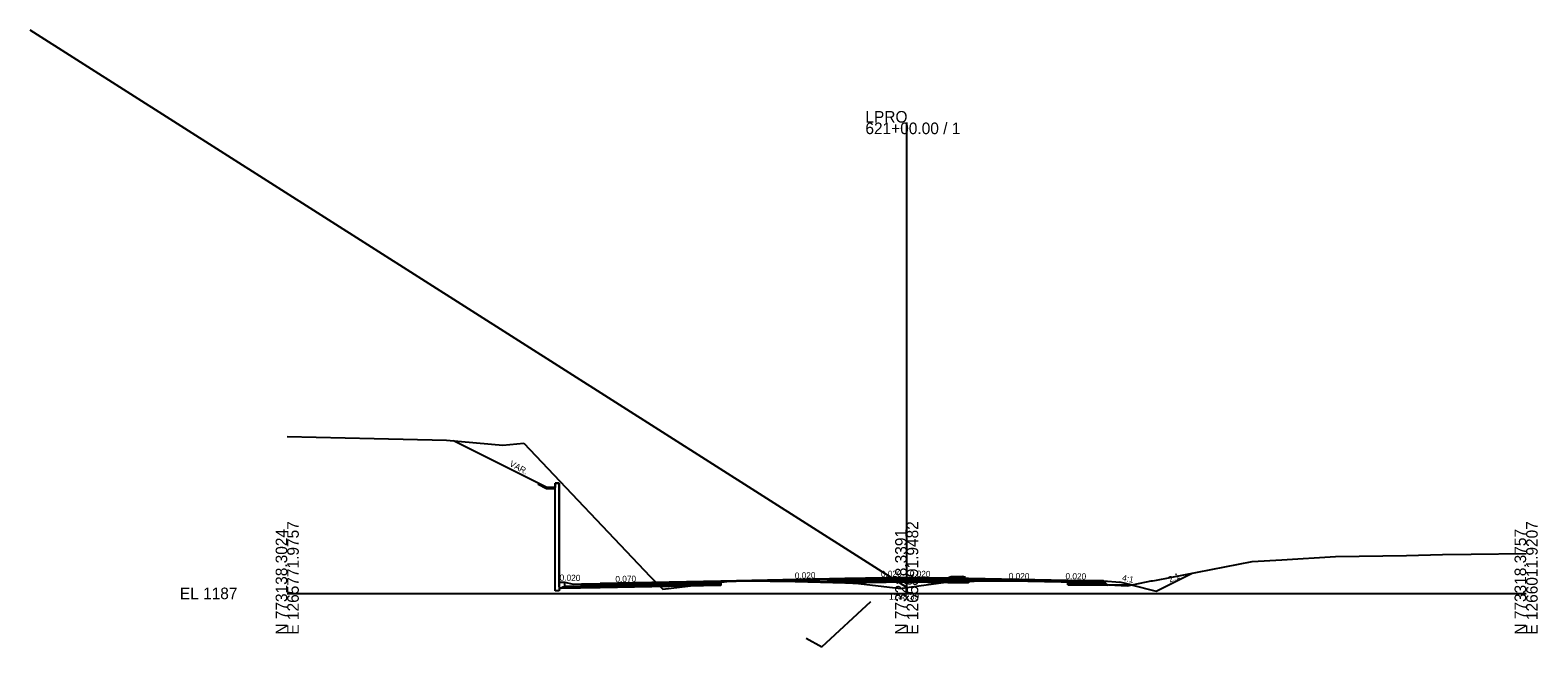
# Model space of a CAD drawing. Extents: x -3833 to 1267678, y -522 to 773248.
# Drawn here: x 2937.8 to 3302.8, y 1987 to 2136.5 of the extents above; entities that cross this region are included whole.
import ezdxf

# ---------------------------------------------------------------- set-up
doc = ezdxf.new("R2010")
doc.units = 0
for name, color, linetype in [('Exist Cross Section Cell', 7, 'Continuous'), ('Exist XS Center Line Elevation Label', 7, 'Continuous'), ('Exist XS Ground Line', 7, 'Continuous'), ('Prop CMT DNC', 7, 'Continuous'), ('Prop CMT Pvmt Course 1', 7, 'Continuous'), ('Prop CMT Pvmt Course 2', 7, 'Continuous'), ('Prop CMT Pvmt Course 3', 7, 'Continuous'), ('Prop CMT Pvmt Course 4', 7, 'Continuous'), ('Prop CMT Shld Paved Course 1', 7, 'Continuous'), ('Prop CMT Shld Paved Course 2', 7, 'Continuous'), ('Prop CMT Shld Paved Course 4', 7, 'Continuous'), ('Prop CMT Slope Grass', 7, 'Continuous'), ('Prop CMT Subgrade Earthwork', 7, 'Continuous'), ('Prop Conc Curb and Gutter', 7, 'Continuous'), ('Prop Corridor Mesh Bottom', 7, 'Continuous'), ('Prop XS Ditch Slope Text', 7, 'Continuous'), ('Prop XS Finish Grade', 7, 'Continuous'), ('Prop XS SE Text', 7, 'Continuous'), ('Scratch_Level_1', 7, 'Continuous'), ('Scratch_Level_5', 7, 'Continuous')]:
    doc.layers.add(name, color=color, linetype=linetype)

msp = doc.modelspace()

# ---------------------------------------------------------------- linework, layer by layer
at = {"layer": 'Exist Cross Section Cell'}
for p, q in [((3150, 2000), (3150, 2114.06)), ((3000, 2000), (3150, 2000)), ((3150, 2000), (3300, 2000))]:
    msp.add_line(p, q, dxfattribs=at)
at = {"layer": 'Exist XS Ground Line'}
for p, q in [((3000, 2038.02), (3021.03, 2037.5)), ((3021.03, 2037.5), (3038.61, 2037.13)), ((3038.61, 2037.13), (3052.2, 2035.94)), ((3052.2, 2035.94), (3057.28, 2036.42)), ((3057.28, 2036.42), (3087.88, 2004.09)), ((3233.63, 2007.72), (3240.83, 2008.12)), ((3240.83, 2008.12), (3253.88, 2008.93)), ((3253.88, 2008.93), (3271.06, 2009.2)), ((3271.06, 2009.2), (3279.79, 2009.39)), ((3279.79, 2009.39), (3286.72, 2009.51)), ((3286.72, 2009.51), (3300, 2009.69)), ((3210.49, 2003.24), (3233.63, 2007.72)), ((3087.88, 2004.09), (3090.95, 2001.04)), ((3090.95, 2001.04), (3106.44, 2002.87)), ((3106.44, 2002.87), (3111.02, 2003.02)), ((3111.02, 2003.02), (3122.99, 2002.92)), ((3122.99, 2002.92), (3135.22, 2002.58)), ((3135.22, 2002.58), (3135.62, 2002.57)), ((3135.62, 2002.57), (3138.31, 2002.42)), ((3138.31, 2002.42), (3148.58, 2001.2)), ((3148.58, 2001.2), (3149.02, 2001.26)), ((3149.02, 2001.26), (3150, 2001.39)), ((3150, 2001.39), (3152.94, 2001.8)), ((3152.94, 2001.8), (3159.49, 2002.7)), ((3159.49, 2002.7), (3160.28, 2002.81)), ((3160.28, 2002.81), (3163.99, 2002.94)), ((3163.99, 2002.94), (3175, 2003.06)), ((3175, 2003.06), (3175.33, 2003.07)), ((3175.33, 2003.07), (3187.65, 2002.83)), ((3187.65, 2002.83), (3188.99, 2002.76)), ((3188.99, 2002.76), (3197.35, 2002.15)), ((3197.35, 2002.15), (3203.47, 2001.86)), ((3203.47, 2001.86), (3209.19, 2003.04)), ((3209.19, 2003.04), (3209.56, 2003.08)), ((3209.56, 2003.08), (3210.49, 2003.24))]:
    msp.add_line(p, q, dxfattribs=at)
at = {"layer": 'Prop CMT Pvmt Course 1'}
for p, q in [((3135, 2003.58), (3105, 2002.98)), ((3105, 2002.98), (3105, 2002.98)), ((3105, 2002.98), (3105, 2002.73)), ((3105, 2002.73), (3106.42, 2002.88)), ((3105, 2002.73), (3105, 2002.73)), ((3105, 2002.73), (3105, 2002.73)), ((3106.42, 2002.88), (3110.92, 2003.04)), ((3110.92, 2003.04), (3135, 2003.33)), ((3135, 2003.33), (3135, 2003.58)), ((3135, 2003.33), (3135, 2003.33)), ((3159.5, 2003.69), (3159.5, 2003.69)), ((3159.5, 2003.69), (3159.5, 2003.44)), ((3159.5, 2003.44), (3159.5, 2003.44)), ((3159.5, 2003.44), (3159.5, 2003.44)), ((3160.25, 2003.42), (3160.25, 2003.7)), ((3160.25, 2003.45), (3160.25, 2003.45)), ((3165, 2003.58), (3164.25, 2003.59)), ((3164.25, 2003.59), (3164.25, 2003.34)), ((3164.25, 2003.34), (3164.25, 2003.34)), ((3164.25, 2003.34), (3165, 2003.33)), ((3189, 2003.1), (3165, 2003.58)), ((3165, 2003.58), (3165, 2003.33)), ((3165, 2003.33), (3165, 2003.58)), ((3165, 2003.58), (3165, 2003.58)), ((3165, 2003.33), (3165, 2003.33)), ((3165, 2003.33), (3189, 2002.85)), ((3165, 2003.33), (3165, 2003.33)), ((3165, 2003.33), (3165, 2003.33)), ((3189, 2002.85), (3189, 2003.1)), ((3189, 2003.1), (3189, 2003.1)), ((3189, 2002.85), (3189, 2002.85)), ((3189, 2002.85), (3189, 2002.85))]:
    msp.add_line(p, q, dxfattribs=at)
at = {"layer": 'Prop CMT Pvmt Course 2'}
for p, q in [((3150, 2003.63), (3135, 2003.33)), ((3135, 2003.33), (3135, 2003.33)), ((3135, 2003.33), (3135, 2003)), ((3135, 2002.99), (3150, 2003.3)), ((3135, 2003), (3135, 2003)), ((3135, 2003), (3135, 2002.99)), ((3135, 2002.99), (3135, 2002.99)), ((3135, 2002.99), (3135, 2002.99)), ((3165, 2003.33), (3150, 2003.63)), ((3150, 2003.3), (3165, 2002.99)), ((3159.5, 2003.44), (3159.5, 2003.44)), ((3159.5, 2003.44), (3159.5, 2003.19)), ((3159.5, 2003.19), (3159.5, 2003.19)), ((3159.5, 2003.19), (3159.5, 2003.19)), ((3160.25, 2003.09), (3160.25, 2003.42)), ((3160.25, 2003.2), (3160.25, 2003.2)), ((3165, 2003.33), (3164.25, 2003.34)), ((3164.25, 2003.34), (3164.25, 2003.09)), ((3164.25, 2003.09), (3164.25, 2003.09)), ((3165, 2002.99), (3165, 2003.33)), ((3165, 2003.33), (3165, 2003.33)), ((3165, 2003.08), (3165, 2003.33)), ((3165, 2003.33), (3165, 2003.33)), ((3165, 2003.08), (3165, 2003.08)), ((3165, 2003.08), (3165, 2003.08)), ((3165, 2002.99), (3165, 2002.99)), ((3165, 2002.99), (3165, 2002.99)), ((3165, 2002.99), (3165, 2002.99))]:
    msp.add_line(p, q, dxfattribs=at)
at = {"layer": 'Prop CMT Pvmt Course 3'}
for p, q in [((3159.5, 2003.19), (3159.5, 2003.19)), ((3159.5, 2003.19), (3159.5, 2002.65)), ((3159.5, 2002.81), (3159.5, 2002.81)), ((3159.5, 2002.81), (3159.5, 2002.81)), ((3160.25, 2002.83), (3160.25, 2003.2)), ((3160.25, 2002.83), (3160.25, 2002.83)), ((3164.25, 2003.09), (3164.25, 2002.72)), ((3164.25, 2002.72), (3164.25, 2002.72)), ((3165, 2002.7), (3165, 2003.08)), ((3165, 2003.08), (3165, 2003.08)), ((3165, 2002.7), (3165, 2002.7)), ((3165, 2002.7), (3165, 2002.7))]:
    msp.add_line(p, q, dxfattribs=at)
at = {"layer": 'Prop CMT Pvmt Course 4'}
for p, q in [((3150, 2003.3), (3135, 2002.99)), ((3135, 2002.99), (3135, 2003)), ((3135, 2003), (3135, 2002.53)), ((3135, 2002.99), (3135, 2002.99)), ((3135, 2002.99), (3135, 2002.99)), ((3135, 2002.53), (3150.01, 2002.84)), ((3165, 2002.99), (3150, 2003.3)), ((3150, 2002.84), (3165, 2002.53)), ((3159.5, 2002.81), (3159.5, 2002.81)), ((3159.5, 2002.81), (3159.5, 2002.65)), ((3160.25, 2002.63), (3160.25, 2002.83)), ((3164.25, 2002.72), (3164.25, 2002.55)), ((3165, 2002.53), (3165, 2002.99)), ((3165, 2002.99), (3165, 2002.99)), ((3165, 2002.99), (3165, 2002.99)), ((3165, 2002.53), (3165, 2002.7)), ((3165, 2002.7), (3165, 2002.7))]:
    msp.add_line(p, q, dxfattribs=at)
at = {"layer": 'Prop CMT Shld Paved Course 1'}
for p, q in [((3071.24, 2002.3), (3075.79, 2002.39)), ((3071.24, 2002.05), (3071.24, 2002.3)), ((3075.79, 2002.14), (3071.24, 2002.05)), ((3071.24, 2002.05), (3071.24, 2002.05)), ((3105, 2002.98), (3075.79, 2002.39)), ((3075.79, 2002.14), (3105, 2002.73)), ((3075.79, 2002.39), (3075.79, 2002.39)), ((3075.79, 2002.39), (3075.79, 2002.14)), ((3075.79, 2002.39), (3075.79, 2002.14)), ((3075.79, 2002.14), (3075.79, 2002.14)), ((3075.79, 2002.14), (3075.79, 2002.14)), ((3105, 2002.73), (3105, 2002.98)), ((3150, 2003.88), (3135, 2003.58)), ((3135, 2003.33), (3150, 2003.63)), ((3135, 2003.58), (3135, 2003.58)), ((3135, 2003.58), (3135, 2003.33)), ((3135, 2003.33), (3135, 2003.33)), ((3135, 2003.33), (3135, 2003.33)), ((3160.25, 2003.67), (3150, 2003.88)), ((3150, 2003.63), (3165, 2003.33)), ((3165, 2003.58), (3164.25, 2003.59)), ((3165, 2003.33), (3165, 2003.58)), ((3165, 2003.58), (3165, 2003.58)), ((3165, 2003.33), (3165, 2003.33)), ((3165, 2003.33), (3165, 2003.33)), ((3189, 2003.1), (3189, 2002.85)), ((3197.65, 2003.02), (3189, 2003.1)), ((3189, 2002.85), (3197.9, 2002.77)), ((3197.9, 2002.77), (3197.65, 2003.02))]:
    msp.add_line(p, q, dxfattribs=at)
at = {"layer": 'Prop CMT Shld Paved Course 2'}
for p, q in [((3071.24, 2002.05), (3075.79, 2002.14)), ((3071.24, 2001.72), (3071.24, 2002.05)), ((3075.79, 2001.81), (3071.24, 2001.72)), ((3105, 2002.73), (3075.79, 2002.14)), ((3075.79, 2001.81), (3105, 2002.39)), ((3075.79, 2002.14), (3075.79, 2001.81)), ((3075.79, 2002.14), (3075.79, 2001.81)), ((3106.42, 2002.88), (3105, 2002.73)), ((3105, 2002.39), (3105, 2002.73)), ((3105, 2002.73), (3105, 2002.73)), ((3105, 2002.73), (3105, 2002.7)), ((3105, 2002.7), (3105.28, 2002.73)), ((3105, 2002.7), (3105, 2002.7)), ((3105.28, 2002.73), (3106.42, 2002.88)), ((3105.28, 2002.73), (3105.28, 2002.73)), ((3105.28, 2002.73), (3105.28, 2002.73)), ((3110.92, 2003.04), (3106.42, 2002.88)), ((3106.42, 2002.88), (3110.92, 2003.04)), ((3122.98, 2003.09), (3110.92, 2003.04)), ((3110.92, 2003.04), (3116.95, 2002.97)), ((3116.95, 2002.97), (3116.95, 2002.97)), ((3116.95, 2002.97), (3122.98, 2002.91)), ((3135, 2003.33), (3122.98, 2003.09)), ((3122.98, 2003.09), (3122.98, 2003.09)), ((3122.98, 2003.09), (3122.98, 2003.09)), ((3122.98, 2002.91), (3122.98, 2002.91)), ((3122.98, 2002.91), (3126.4, 2002.82)), ((3126.4, 2002.82), (3135, 2002.99)), ((3126.4, 2002.82), (3126.4, 2002.82)), ((3135, 2002.99), (3135, 2003.33)), ((3135, 2002.99), (3135, 2002.99)), ((3135, 2002.99), (3135, 2002.99)), ((3174.99, 2003.13), (3165, 2003.33)), ((3165, 2003.33), (3165, 2002.99)), ((3165, 2002.99), (3165, 2002.99)), ((3165, 2002.99), (3165, 2002.99)), ((3165, 2002.99), (3166.34, 2002.97)), ((3166.34, 2002.97), (3174.99, 2003.06)), ((3175.32, 2003.12), (3174.99, 2003.13)), ((3174.99, 2003.13), (3174.99, 2003.13)), ((3174.99, 2003.06), (3175.32, 2003.07)), ((3174.99, 2003.06), (3174.99, 2003.06)), ((3187.44, 2002.88), (3175.32, 2003.12)), ((3175.32, 2003.12), (3175.32, 2003.12)), ((3175.32, 2003.07), (3175.32, 2003.07)), ((3175.32, 2003.07), (3187.44, 2002.83)), ((3187.64, 2002.87), (3187.44, 2002.88)), ((3187.44, 2002.88), (3187.44, 2002.88)), ((3187.44, 2002.83), (3187.44, 2002.83)), ((3187.44, 2002.83), (3187.64, 2002.83)), ((3188.95, 2002.85), (3187.64, 2002.87)), ((3187.64, 2002.87), (3187.64, 2002.87)), ((3187.64, 2002.87), (3187.64, 2002.87)), ((3187.64, 2002.83), (3187.64, 2002.83)), ((3187.64, 2002.83), (3187.64, 2002.83)), ((3187.64, 2002.83), (3188.95, 2002.76)), ((3189, 2002.85), (3188.95, 2002.85)), ((3188.95, 2002.85), (3188.95, 2002.85)), ((3188.95, 2002.76), (3188.95, 2002.76)), ((3188.95, 2002.76), (3189, 2002.76)), ((3189, 2002.76), (3189, 2002.85)), ((3189, 2002.85), (3189, 2002.51)), ((3197.9, 2002.77), (3189, 2002.85)), ((3189, 2002.76), (3189, 2002.76)), ((3189, 2002.51), (3198.23, 2002.43)), ((3198.23, 2002.43), (3197.9, 2002.77))]:
    msp.add_line(p, q, dxfattribs=at)
at = {"layer": 'Prop CMT Shld Paved Course 4'}
for p, q in [((3066.28, 2001.16), (3066.74, 2001.63)), ((3075.79, 2001.35), (3066.28, 2001.16)), ((3066.74, 2001.63), (3067.24, 2001.64)), ((3067.24, 2001.64), (3075.79, 2001.81)), ((3075.79, 2001.81), (3105, 2002.39)), ((3105, 2001.93), (3075.79, 2001.35)), ((3075.79, 2001.81), (3075.79, 2001.35)), ((3075.79, 2001.35), (3075.79, 2001.81)), ((3105, 2002.39), (3105, 2001.93)), ((3189, 2002.51), (3189, 2002.05)), ((3197.73, 2002.44), (3189, 2002.51)), ((3189, 2002.05), (3198.7, 2001.97)), ((3198.23, 2002.43), (3197.73, 2002.44)), ((3198.7, 2001.97), (3198.23, 2002.43))]:
    msp.add_line(p, q, dxfattribs=at)
at = {"layer": 'Prop CMT Slope Grass'}
for p, q in [((3065.86, 2002.75), (3067.24, 2002.72)), ((3197.65, 2003.02), (3201.65, 2002.7)), ((3204.38, 2002.04), (3201.65, 2002.7))]:
    msp.add_line(p, q, dxfattribs=at)
at = {"layer": 'Prop CMT Subgrade Earthwork'}
for p, q in [((3065.86, 2002.75), (3065.86, 2001.57)), ((3065.86, 2001.57), (3066.28, 2001.16)), ((3105, 2001.93), (3066.28, 2001.16)), ((3105, 2001.93), (3105, 2002.7)), ((3150, 2002.84), (3135, 2002.53)), ((3135, 2002.53), (3135, 2002.59)), ((3165, 2002.53), (3150, 2002.84)), ((3165, 2002.95), (3165, 2002.53)), ((3189, 2002.05), (3189, 2002.76)), ((3198.7, 2001.97), (3189, 2002.05)), ((3204.38, 2002.04), (3198.7, 2001.97))]:
    msp.add_line(p, q, dxfattribs=at)
at = {"layer": 'Prop Conc Curb and Gutter'}
for p, q in [((3060.78, 2026.36), (3060.93, 2026.66)), ((3062.78, 2025.36), (3060.78, 2026.36)), ((3062.86, 2025.69), (3060.93, 2026.66)), ((3064.85, 2000.63), (3064.86, 2026.69)), ((3064.86, 2026.69), (3065.86, 2026.69)), ((3065.86, 2026.69), (3065.86, 2026.69)), ((3065.86, 2026.69), (3065.86, 2002.19)), ((3064.86, 2025.36), (3062.78, 2025.36)), ((3064.86, 2025.69), (3062.86, 2025.69)), ((3065.86, 2002.19), (3065.86, 2002.19)), ((3065.86, 2002.19), (3065.86, 2000.63)), ((3067.24, 2001.64), (3067.24, 2002.72)), ((3067.24, 2002.72), (3069.24, 2002.22)), ((3069.24, 2001.68), (3067.24, 2001.64)), ((3067.24, 2001.64), (3067.24, 2001.64)), ((3067.24, 2001.64), (3067.24, 2001.64)), ((3069.24, 2002.22), (3071.24, 2002.3)), ((3069.24, 2002.22), (3069.24, 2002.22)), ((3069.24, 2002.22), (3069.24, 2002.22)), ((3071.24, 2001.72), (3069.24, 2001.68)), ((3069.24, 2001.68), (3069.24, 2001.68)), ((3071.24, 2002.3), (3071.24, 2001.72)), ((3071.24, 2001.72), (3071.24, 2001.72)), ((3160.25, 2003.77), (3160.26, 2003.94)), ((3160.25, 2003.64), (3160.25, 2003.77)), ((3160.25, 2003.7), (3160.25, 2003.7)), ((3164.25, 2003.58), (3160.25, 2003.64)), ((3160.25, 2003.58), (3160.25, 2003.58)), ((3160.26, 2003.94), (3160.81, 2004.12)), ((3160.26, 2003.87), (3160.26, 2003.87)), ((3160.81, 2004.12), (3163.49, 2004.1)), ((3161.01, 2004.12), (3161.01, 2004.12)), ((3164.24, 2003.85), (3163.49, 2004.1)), ((3164.25, 2003.68), (3164.24, 2003.85)), ((3164.24, 2003.76), (3164.24, 2003.76)), ((3164.25, 2003.68), (3164.25, 2003.58)), ((3164.25, 2003.59), (3164.25, 2003.59)), ((3164.25, 2003.47), (3164.25, 2003.47)), ((3065.86, 2000.63), (3064.85, 2000.63)), ((3064.85, 2000.63), (3064.85, 2000.63)), ((3065.86, 2000.63), (3065.86, 2000.63)), ((3065.86, 2000.63), (3065.86, 2000.63))]:
    msp.add_line(p, q, dxfattribs=at)
at = {"layer": 'Prop Corridor Mesh Bottom'}
for p, q in [((3075.79, 2002.39), (3075.79, 2002.14)), ((3135, 2003.58), (3135, 2003.33)), ((3165, 2003.58), (3165, 2003.33))]:
    msp.add_line(p, q, dxfattribs=at)
at = {"layer": 'Prop XS Finish Grade'}
for p, q in [((3060.93, 2026.66), (3040.28, 2036.98)), ((3062.86, 2025.69), (3060.93, 2026.66)), ((3065.86, 2026.69), (3064.86, 2026.69)), ((3064.86, 2026.69), (3064.86, 2025.69)), ((3065.86, 2001.57), (3065.86, 2026.69)), ((3064.86, 2025.69), (3062.86, 2025.69)), ((3204.38, 2002.04), (3210.38, 2000.54))]:
    msp.add_line(p, q, dxfattribs=at)
msp.add_lwpolyline([(3210.38, 2000.54), (3212.38, 2001.54), (3219.12, 2004.91)], dxfattribs=at)
at = {"layer": 'Scratch_Level_1'}
msp.add_line((3150, 2001.39), (2937.75, 2136.45), dxfattribs=at)
at = {"layer": 'Scratch_Level_5'}
for p, q in [((3129.46, 1987.05), (3141.31, 1998.07)), ((3125.67, 1989.15), (3129.46, 1987.05))]:
    msp.add_line(p, q, dxfattribs=at)

# ---------------------------------------------------------------- texts
at = {"layer": 'Exist Cross Section Cell'}
for s, p in [('621+00.00 / 1', (3140, 2111.26)), ('LPRO', (3140, 2114.06)), ('EL 1187', (2974, 1998.6))]:
    msp.add_text(s, height=2.8, dxfattribs=at).set_placement(p)
for s, p in [('N 773138.3024', (3000, 1990)), ('E 1265771.9757', (3002.8, 1990)), ('N 773228.3391', (3150, 1990)), ('E 1265891.9482', (3152.8, 1990)), ('N 773318.3757', (3300, 1990)), ('E 1266011.9207', (3302.8, 1990))]:
    msp.add_text(s, height=2.8, rotation=90, dxfattribs=at).set_placement(p)
at = {"layer": 'Exist XS Center Line Elevation Label'}
msp.add_text('1188.39', height=1.5, dxfattribs=at).set_placement((3145.74, 1998.51))
at = {"layer": 'Prop CMT DNC'}
for p in [(3066.89, 2026.26), (3071.24, 2002.3), (3075.79, 2002.39), (3075.79, 2002.39), (3135, 2003.58), (3135, 2003.58), (3150, 2003.88), (3165, 2003.58), (3165, 2003.58), (3189, 2003.1), (3189, 2003.1)]:
    msp.add_text('X', height=0.00025, dxfattribs=at).set_placement(p)
at = {"layer": 'Prop XS Ditch Slope Text'}
for s, rotation, p in [('VAR.', 331.3485, (3053.68, 2030.96)), ('4:1', 348.3072, (3202.07, 2003.1)), ('2:1', 23.8989, (3213.75, 2002.59))]:
    msp.add_text(s, height=1.5, rotation=rotation, dxfattribs=at).set_placement(p)
at = {"layer": 'Prop XS SE Text'}
for s, rotation, p in [('0.020', 358.8542, (3065.95, 2003.09)), ('0.070', 1.397, (3079.48, 2002.7)), ('0.020', 1.299, (3122.92, 2003.55)), ('0.020', 1.26, (3143.79, 2003.95)), ('0.020', 358.8542, (3150.73, 2004.04)), ('0.020', 358.8542, (3174.69, 2003.48)), ('0.020', 358.8542, (3188.44, 2003.45))]:
    msp.add_text(s, height=1.5, rotation=rotation, dxfattribs=at).set_placement(p)

doc.saveas('drawing.dxf')
